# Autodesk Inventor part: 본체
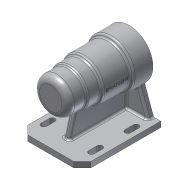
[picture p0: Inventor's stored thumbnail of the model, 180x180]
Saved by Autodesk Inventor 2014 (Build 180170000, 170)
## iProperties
Created: 2017-09
Part Number: 본체
Material: 알루미늄 6061
Document SubType Name: Modeling
Designer: user
Density: 2.71 g/cm^3
Appearance: 알루미늄 - 평지
Mass: 698.011 g
Surface Area: 708.903 cm^2
Volume: 257.569 cm^3
Author: user
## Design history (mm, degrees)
sketch "스케치1"
  geometry: L1 (0, 56)-(0, -56); L2 (0, 56)-(25, 56); L3 (25, 56)-(25, 31); L4 (25, 31)-(27, 31); L5 (27, 31)-(27, 11); L6 (27, 11)-(30, 11); L7 (30, 11)-(30, -28); L8 (30, -28)-(34, -28); L9 (34, -28)-(34, -56); L10 (34, -56)-(0, -56); 2 further points
  constraints: 20 end point, 6 parallel, 3 perpendicular, 1 coincident, 1 midpoint, 1 vertical
  dimensions: "d0" = 112 distance of L1.start L1.end; "d1" = 50 diameter of L3 L1; "d2" = 54 diameter of L5 L1; "d3" = 60 diameter of L7 L1; "d4" = 25 vertical distance of L2.end L4.end; "d5" = 45 distance between parallel lines of L6 L2; "d6" = 84 distance between parallel lines of L2 L8; "d7" = 112 distance between parallel lines of L2 L10 (derived); "d8" = 68 diameter of L9 L1
revolve "회전1" sketch "스케치1" stored, may be unused: angle "d9" = 90 deg
sketch "스케치2"
  geometry: C1 r 34 at (0, 0) reference; C2 r 21 at (0, 0)
  constraints: 1 centre point, 1 coincident
  dimensions: "d10" = 42 diameter of C2
extrude "돌출1" cut sketch "스케치2" distance "d11" = 15; taper "d12" = 0 deg
sketch "스케치3"
  geometry: C1 r 21 at (0, 0) reference; C2 r 24 at (0, 0)
  constraints: 1 centre point, 1 coincident
  dimensions: "d13" = 48 diameter of C2
extrude "돌출2" cut sketch "스케치3" distance "d14" = 54; taper "d15" = 0 deg
sketch "스케치4"
  geometry: C1 r 24 at (0, 0) reference; C2 r 21 at (0, 0)
  constraints: 1 centre point, 1 coincident
  dimensions: "d16" = 42 diameter of C2
extrude "돌출3" cut sketch "스케치4" distance "d17" = 12; taper "d18" = 0 deg
sketch "스케치5"
  geometry: C1 r 21 at (0, 0) reference; C2 r 17.5 at (0, 0)
  constraints: 1 centre point, 1 coincident
  dimensions: "d19" = 35 diameter of C2
extrude "돌출4" cut sketch "스케치5" distance "d20" = 18; taper "d21" = 0 deg
sketch "스케치6"
  geometry: C1 r 17.5 at (0, 0) reference; C2 r 16 at (0, 0)
  constraints: 1 centre point, 1 coincident
  dimensions: "d22" = 32 diameter of C2
extrude "돌출5" cut sketch "스케치6" distance "d23" = 4; taper "d24" = 0 deg
sketch "스케치7"
  geometry: C1 r 16 at (0, 0) reference; C2 r 10.5 at (0, 0)
  constraints: 1 centre point, 1 coincident
  dimensions: "d25" = 21 diameter of C2
extrude "돌출6" cut sketch "스케치7" distance "d26" = 3; taper "d27" = 0 deg
node "작업 평면1"
sketch "스케치8"
  geometry: L1 (-45, 56)-(45, 56); L2 (45, 56)-(45, -56); L3 (45, -56)-(-45, -56); L4 (-45, -56)-(-45, 56); L5 (-45, 56)-(45, -56); L6 (-45, -56)-(45, 56); 2 further points
  constraints: 12 end point, 2 parallel, 1 coincident, 1 horizontal, 1 midpoint, 1 perpendicular
  dimensions: "d29" = 90 distance of L2.end L3.end; "d30" = 112 distance of L1.end L2.end
extrude "돌출7" join sketch "스케치8" distance "d31" = 8; taper "d32" = 0 deg
sketch "스케치9"
  geometry: L1 (45, -62)-(-45, -62) reference; L2 (-21.9, -26.008)-(-35, -62); L3 (21.9, -26.008)-(35, -62); L4 (0, 0)-(0, -34); L5 (-35, -62)-(35, -62); A1 r 34 centre (0, 0) between (-21.9, -26.008) and (21.9, -26.008) reference; A2 r 34 centre (0, 0) between (-21.9, -26.008) and (21.9, -26.008)
  constraints: 8 end point, 6 point on circle, 2 point on line, 1 centre point, 1 collinear, 1 perpendicular
  dimensions: "d33" = 110 deg angle of L1 L3; "d34" = 110 deg angle of L1 L2; "d35" = 10 distance of L1.end L2.end; "d36" = 10 distance of L1.start L3.end
extrude "돌출8" join sketch "스케치9" distance "d37" = 8; taper "d38" = 0 deg
sketch "스케치10" dims "d39" = 52
  geometry: L1 (80, 8)-(90, 8) reference; L2 (45, 70)-(45, 96); A1 r 34 centre (45, 70) between (66.9, 43.992) and (23.1, 43.992) reference; 1 further point
  constraints: 2 coincident, 2 end point, 1 perpendicular, 1 vertical alignment, 2 other
hole "구멍1" sketch "스케치10" at (45, 96) diameter "d40" = 3.242; stored, may be unused: countersink angle "d44" = 90 deg, drill point angle "d46" = 118 deg; dims "d41" = 8, "d42" = 4, "d43" = 2, "d45" = 11
chamfer "모따기1" distance "d50" = 12; stored, may be unused: second distance "d51" = 2, angle "d52" = 45 deg
chamfer "모따기2" distance "d53" = 1; stored, may be unused: second distance "d54" = 2, angle "d55" = 45 deg
sketch "스케치11"
  geometry: L1 (-33, -56)-(33, -56) reference; L2 (-45, 56)-(45, 56) reference; L3 (0, -56)-(0, 56); L4 (-38, -20)-(-38, -32); L5 (-30, -32)-(-30, -20); L6 (-38, 32)-(-38, 20); L7 (-30, 20)-(-30, 32); L8 (30, -20)-(30, -32); L9 (38, -32)-(38, -20); L10 (30, 32)-(30, 20); L11 (38, 20)-(38, 32); A1 r 4 centre (-34, -32) between (-38, -32) and (-30, -32); A2 r 4 centre (-34, -20) between (-30, -20) and (-38, -20); A3 r 4 centre (-34, 32) between (-30, 32) and (-38, 32); A4 r 4 centre (-34, 20) between (-38, 20) and (-30, 20); A5 r 4 centre (34, -20) between (38, -20) and (30, -20); A6 r 4 centre (34, -32) between (30, -32) and (38, -32); A7 r 4 centre (34, 32) between (38, 32) and (30, 32); A8 r 4 centre (34, 20) between (30, 20) and (38, 20); 1 further point
  constraints: 18 end point, 16 point on circle, 12 tangent, 8 centre point, 5 vertical alignment, 2 midpoint
  dimensions: "d95" = 4 radius of A1; "d96" = 4 radius of A2; "d97" = 4 radius of A4; "d98" = 4 radius of A3; "d99" = 4 radius of A6; "d100" = 4 radius of A5; "d101" = 4 radius of A8; "d102" = 4 radius of A7; "d103" = 24 vertical distance of L2.end A7.centre; "d104" = 12 distance of A8.centre A7.centre; "d105" = 40 distance of A5.centre A8.centre; "d106" = 12 distance of A5.centre A6.centre; "d107" = 24 distance from line of L2 A3.centre; "d108" = 12 distance of A4.centre A3.centre; "d109" = 40 distance of A2.centre A4.centre; "d110" = 12 distance of A1.centre A2.centre; "d111" = 34 distance from line of L3 A1.centre; "d112" = 34 horizontal distance of L3.start A6.centre
extrude "돌출9" cut sketch "스케치11" stored distance "d75" = 8; taper "d76" = 0 deg
sketch "스케치12"
  geometry: L1 (-62, 44)-(-62, -56) reference; L2 (-62, 44)-(-62, 56) reference; L3 (-70, 44)-(-62, 44) reference; L4 (-70, -56)-(-70, 44) reference; L5 (-70, -56)-(-62, -56) reference; L6 (-62, 44)-(-62, -56) reference; L7 (-27, 31)-(-27, 11) reference; L8 (-30, 11)-(-30, -28) reference; L9 (-30, 11)-(30, 11) reference; L10 (-27, 31)-(27, 31) reference; L11 (-25, 56)-(-25, 31) reference; L12 (-27, 24.622)-(-62, 34); L13 (-62, 56)-(-70, 56) reference; 1 further point
  constraints: 2 end point, 2 point on line
  dimensions: "d77" = 105 deg angle of L1 L12; "d78" = 22 distance from line of L13 L12.end
feature "리브1" sketch "스케치12" dims "d79" = 1, "d80" = 8, "d81" = 0, "d82" = 0, "d83" = 1, "d84" = 1
fillet "모깎기1" dims "d85" = 3
fillet "모깎기2" dims "d86" = 3
fillet "모깎기3" dims "d87" = 9
fillet "모깎기4" dims "d88" = 3
fillet "모깎기5" dims "d89" = 3
fillet "모깎기6" dims "d90" = 0.3
node "작업 평면2"
sketch "스케치13"
  geometry: L1 (-24.711, -56)-(34, -56) reference; 2 further points
  constraints: 1 vertical alignment, 1 other
  dimensions: "d92" = 48 distance from line of L1 point (0, -8)
feature "엠보싱1" sketch "스케치13" dims "d93" = 0.5, "d94" = 0
node "솔리드1"
pattern_circular "원형 패턴1" dims angle "d48" = 360 deg
node "투영된 루프1"
other parameters: "d91" = 35
